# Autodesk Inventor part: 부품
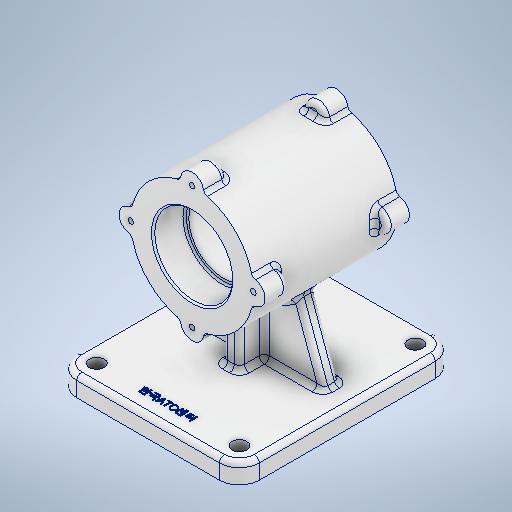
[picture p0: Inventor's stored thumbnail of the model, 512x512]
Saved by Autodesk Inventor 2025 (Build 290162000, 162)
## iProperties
Created: 2024-08
Part Number: 부품
Material: 알루미늄 6061
Document SubType Name: Modeling
Designer: hsj03
Density: 2.7 g/cm^3
Appearance: 알루미늄 - 평지
Mass: 1215.37 g
Surface Area: 796.667 cm^2
Volume: 450.138 cm^3
Author: hsj03
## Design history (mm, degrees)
sketch "스케치1"
  geometry: C1 r 37 at (0, 0); 1 further point
  constraints: 1 centre point, 1 coincident
  dimensions: "d1" = 37 radius of C1
extrude "돌출1" new body sketch "스케치1" stored distance "d2" = 87; taper "d3" = 0 deg
node "작업 평면1"
sketch "스케치2"
  geometry: L1 (55, 70)-(55, -60); L2 (55, -60)-(-55, -60); L3 (-55, -60)-(-55, 70); L4 (-55, 70)-(55, 70); L5 (-37, -43.5)-(37, -43.5) reference; L6 (37, 43.5)-(-37, 43.5) reference; L7 (0, 70)-(0, -60); L8 (55, 0)-(-55, 0); 2 further points
  constraints: 12 end point, 3 midpoint, 2 coincident, 2 parallel, 2 point on line, 2 vertical, 1 horizontal, 1 perpendicular
  dimensions: "d6" = 70 distance of L1.start L8.start; "d7" = 130 distance between parallel lines of L4 L2; "d8" = 110 distance of L1.end L2.end
extrude "돌출2" join sketch "스케치2" distance "d9" = 12; taper "d10" = 0 deg
sketch "스케치3"
  geometry: L1 (-5, -20)-(-5, 20); L2 (-5, 20)-(5, 20); L3 (5, 20)-(5, -20); L4 (5, -20)-(-5, -20); L5 (-5, -20)-(5, 20); L6 (-5, 20)-(5, -20); L7 (-55, -70)-(55, -70) reference; 3 further points
  constraints: 12 end point, 3 midpoint, 2 parallel, 1 coincident, 1 perpendicular, 1 vertical
  dimensions: "d11" = 70 distance from line of L7 point (0, 0); "d12" = 10 distance of L1.end L2.end; "d13" = 40 distance of L1.start L1.end
extrude "돌출3" join sketch "스케치3" stored distance "d14" = 12; taper "d15" = 0 deg
node "작업 평면2"
sketch "스케치4"
  geometry: L1 (-25.336, -26.964)-(25.336, -26.964); L2 (25.336, -26.964)-(41, -70); L3 (41, -70)-(-41, -70); L4 (-41, -70)-(-25.336, -26.964); L5 (55, -70)-(-55, -70) reference; L6 (0, 0)-(0, -82); L7 (-77, -82)-(77, -82) reference; L8 (-55, -82)-(-55, -70) reference; A1 r 37 centre (0, 0) between (-25.336, -26.964) and (25.336, -26.964) reference
  constraints: 10 end point, 2 horizontal, 2 point on circle, 1 coincident, 1 midpoint, 1 point on line, 1 vertical
  dimensions: "d16" = 110 deg angle of L5 L2; "d17" = 110 deg angle of L5 L4; "d18" = 14 distance of L5.start L2.end; "d89" = 14 distance from line of L8 L3.end (derived)
extrude "돌출4" join sketch "스케치4" stored distance "d19" = 10; taper "d20" = 0 deg
sketch "스케치5"
  geometry: C1 r 37 at (0, 0) reference; C2 r 7 at (0, 37); 1 further point
  constraints: 2 vertical alignment, 1 centre point, 1 other
  dimensions: "d22" = 7 radius of C2
extrude "돌출5" join sketch "스케치5" distance "d23" = 14; taper "d24" = 0 deg
fillet "모깎기1" dims "d28" = 12
sketch "스케치6"
  geometry: A1 r 37 centre (0, 0) between (36.338, 6.969) and (6.969, 36.338) reference; 1 further point
  constraints: 1 coincident
hole "구멍1" sketch "스케치6" at (0, 0) diameter "d29" = 42; stored, may be unused: countersink angle "d33" = 90 deg, drill point angle "d35" = 118 deg; dims "d30" = 6, "d31" = 47, "d32" = 19, "d34" = 8
sketch "스케치7"
  geometry: A1 r 37 centre (0, 0) between (36.338, 6.969) and (6.969, 36.338) reference; 1 further point
  constraints: 1 coincident
hole "구멍2" sketch "스케치7" at (0, 0) diameter "d36" = 42; stored, may be unused: countersink angle "d40" = 90 deg, drill point angle "d42" = 118 deg; dims "d37" = 6, "d38" = 47, "d39" = 19, "d41" = 8
fillet "모깎기2" dims "d43" = 1
chamfer "모따기1" distance "d44" = 1; stored, may be unused: second distance "d45" = 2, angle "d46" = 45 deg
sketch "스케치8"
  geometry: A1 r 7 centre (-37, 0) between (-36.338, 6.969) and (-36.338, -6.969) reference; A2 r 7 centre (0, 37) between (6.969, 36.338) and (-6.969, 36.338) reference; A3 r 7 centre (0, -37) between (-6.969, -36.338) and (6.969, -36.338) reference; A4 r 7 centre (37, 0) between (36.338, -6.969) and (36.338, 6.969) reference; 5 further points
  constraints: 4 coincident
hole "구멍3" sketch "스케치8" at (-37, 0), (0, 37), (0, -37), (37, 0) diameter "d47" = 3.242; stored, may be unused: countersink angle "d51" = 90 deg, drill point angle "d53" = 120 deg; dims "d48" = 8, "d49" = 47, "d50" = 19, "d52" = 10
sketch "스케치9"
  geometry: A1 r 7 centre (0, 37) between (6.969, 36.338) and (-6.969, 36.338) reference; A2 r 7 centre (-37, 0) between (-36.338, 6.969) and (-36.338, -6.969) reference; A3 r 7 centre (0, -37) between (-6.969, -36.338) and (6.969, -36.338) reference; A4 r 7 centre (37, 0) between (36.338, -6.969) and (36.338, 6.969) reference; 4 further points
  constraints: 4 coincident
hole "구멍4" sketch "스케치9" at (0, 37), (-37, 0), (0, -37), (37, 0) diameter "d54" = 3.242; stored, may be unused: countersink angle "d58" = 90 deg, drill point angle "d60" = 120 deg; dims "d55" = 8, "d56" = 4, "d57" = 2, "d59" = 10
sketch "스케치10"
  geometry: L1 (0, -70)-(0, 60); L2 (-43, -70)-(43, -70) reference; L3 (43, 60)-(-43, 60) reference; L4 (-55, -5)-(55, -5); L5 (-55, 48)-(-55, -58) reference; L6 (55, -58)-(55, 48) reference; 4 further points
  constraints: 4 end point, 4 midpoint, 2 symmetric about line, 1 horizontal, 1 vertical
  dimensions: "d68" = 86 distance of point (43, -58) point (-43, -58); "d69" = 106 distance of point (-43, -58) point (-43, 48); "d70" = 12 distance from line of L3 point (-43, 48); "d87" = 12 distance from line of L5 point (-43, 48)
hole "구멍5" sketch "스케치10" at (-43, 48), (43, 48), (43, -58), (-43, -58) diameter "d61" = 9; stored, may be unused: countersink angle "d65" = 90 deg, drill point angle "d67" = 0 deg; dims "d62" = 8, "d63" = 4, "d64" = 2, "d66" = 10
fillet "모깎기3" dims "d71" = 3
fillet "모깎기4" dims "d72" = 3
fillet "모깎기5" dims "d73" = 3
fillet "모깎기6" dims "d80" = 3
sketch "스케치13"
  geometry: L1 (-43, -70)-(43, -70) reference; 3 further points
  constraints: 1 midpoint, 1 vertical alignment, 1 other
  dimensions: "d83" = 12 distance of point (0, -70) point (0, -58); "d84" = 58 distance of point (0, 0) point (0, -58) (derived)
feature "엠보싱1" sketch "스케치13" dims "d85" = 0.5, "d86" = 0
fillet "모깎기7" dims "d88" = 3
feature "͞耀͠耀͢耀ͤ耀ͦ耀ͨ耀ͪ耀ͬ耀" dims "d1" = 37, "d2" = 87, "d3" = 0, "d4" = -82, "d6" = 70, "d7" = 130, "d8" = 110, "d9" = 12, "d10" = 0, "d11" = 70, "d12" = 10, "d13" = 40, "d14" = 12, "d15" = 0, "d16" = 110 deg, "d17" = 110 deg, "d18" = 14, "d19" = 10, "d20" = 0, "d22" = 7, "d23" = 14, "d24" = 0, "d25" = 40, "d26" = 360 deg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
node "솔리드1"
pattern_circular "원형 패턴1" dims angle "d26" = 360 deg
mirror "미러1"
node "투영된 루프1"
feature "A9D066F2-1C7D-4E18-AEED-F7BC21143FA4" dims "d29" = 42, "d30" = 6, "d31" = 47, "d32" = 19, "d33" = 90 deg, "d34" = 8, "d35" = 118 deg
